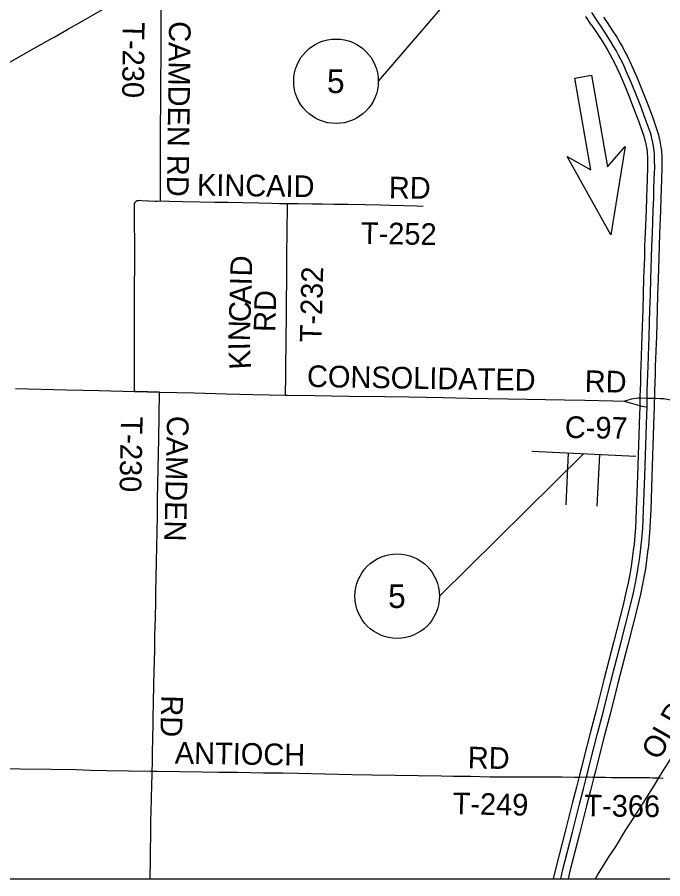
# Model space of a CAD drawing. Extents: x 1341221 to 1914484, y 79347 to 658398.
# Drawn here: x 1374791 to 1392220, y 580425 to 603681 of the extents above; entities that cross this region are included whole.
import ezdxf

# ---------------------------------------------------------------- set-up
doc = ezdxf.new("R2010")
doc.units = 0
for name, color, linetype in [('GM_X_County', 7, 'Continuous'), ('GM_X_County_Road_Text', 7, 'Continuous'), ('GM_X_Major_Lake_Text', 7, 'Continuous'), ('GM_X_Major_River_Text', 7, 'Continuous'), ('GM_X_Minor_Lake_Text', 7, 'Continuous'), ('GM_X_Minor_River', 7, 'Continuous'), ('GM_X_State_Location', 7, 'Continuous'), ('GM_X_Township_Road_Text', 7, 'Continuous'), ('GM_X_Township_Text', 7, 'Continuous'), ('GM_X_Unincorporated', 7, 'Continuous'), ('GM_X_US_Shield', 7, 'Continuous')]:
    doc.layers.add(name, color=color, linetype=linetype)

msp = doc.modelspace()

# ---------------------------------------------------------------- linework, layer by layer
at = {"layer": 'GM_X_County'}
msp.add_line((1390297, 603467), (1390145, 603700), dxfattribs=at)
for points in [[(1390624, 603681), (1390719, 603535), (1390865, 603315), (1390977, 603139), (1391072, 602981), (1391131, 602878), (1391200, 602751), (1391256, 602643), (1391333, 602483), (1391414, 602304), (1391526, 602042), (1391672, 601684), (1391796, 601366), (1391930, 601018), (1392037, 600724), (1392072, 600613), (1392102, 600508), (1392127, 600409)], [(1390297, 603467), (1390394, 603320), (1390538, 603103), (1390645, 602934), (1390735, 602784), (1390790, 602687), (1390856, 602568), (1390906, 602470), (1390979, 602318), (1391057, 602147), (1391166, 601892), (1391310, 601539), (1391433, 601225), (1391565, 600881), (1391668, 600597), (1391699, 600501), (1391725, 600408), (1391748, 600315)], [(1391748, 600315), (1391750, 600309), (1391771, 600209), (1391786, 600117), (1391795, 600041), (1391801, 599975), (1391804, 599935)], [(1392127, 600409), (1392130, 600396), (1392154, 600282), (1392172, 600172), (1392183, 600082), (1392190, 600008), (1392193, 599967)], [(1391804, 599948), (1391806, 599823), (1391807, 599638), (1391797, 599308), (1391788, 599065), (1391780, 598815), (1391768, 598471)], [(1392194, 599954), (1392196, 599828), (1392197, 599634), (1392186, 599294), (1392178, 599051), (1392170, 598802), (1392158, 598457)], [(1391768, 598471), (1391744, 597858), (1391731, 597511), (1391724, 597191), (1391704, 596636), (1391691, 596194), (1391679, 595798), (1391657, 595083), (1391629, 594272), (1391622, 594055), (1391615, 593838), (1391606, 593593), (1391605, 593476)], [(1392157, 598456), (1392134, 597843), (1392121, 597499), (1392113, 597180), (1392094, 596623), (1392081, 596183), (1392069, 595786), (1392047, 595070), (1392019, 594259), (1392012, 594042), (1392005, 593825), (1391996, 593583), (1391994, 593470)], [(1391605, 593476), (1391603, 593403), (1391601, 593328)], [(1391601, 593325), (1391600, 593168), (1391593, 592965)], [(1391991, 593321), (1391990, 593160), (1391983, 592952)], [(1391994, 593470), (1391993, 593395), (1391991, 593318)], [(1391593, 592965), (1391537, 591298), (1391506, 590391), (1391495, 590118), (1391483, 589911), (1391466, 589686), (1391444, 589453), (1391425, 589285), (1391398, 589073), (1391366, 588856), (1391329, 588640), (1391284, 588412), (1391236, 588191), (1391147, 587820), (1390897, 586838), (1390628, 585799), (1390418, 584965), (1390271, 584396), (1390102, 583725), (1390026, 583428), (1389974, 583226)], [(1391983, 592952), (1391927, 591285), (1391896, 590376), (1391884, 590099), (1391872, 589885), (1391855, 589652), (1391832, 589413), (1391812, 589239), (1391785, 589020), (1391751, 588794), (1391712, 588569), (1391666, 588333), (1391616, 588104), (1391526, 587727), (1391275, 586741), (1391006, 585703), (1390796, 584869), (1390649, 584299), (1390480, 583629), (1390404, 583331), (1390352, 583129)], [(1389974, 583226), (1389890, 582902), (1389785, 582490), (1389594, 581735), (1389336, 580725), (1389264, 580425)], [(1390352, 583128), (1390268, 582805), (1390163, 582393), (1389972, 581639), (1389715, 580631), (1389665, 580425)]]:
    msp.add_lwpolyline(points, dxfattribs=at)
for centre in [(1383398, 601952), (1385049, 588054)]:
    msp.add_circle(centre, 1141, dxfattribs=at)
at = {"layer": 'GM_X_County_Road_Text'}
for p, q in [((1387422, 605318), (1384539, 601952)), ((1386190, 588054), (1390089, 591901))]:
    msp.add_line(p, q, dxfattribs=at)
at = {"layer": 'GM_X_Minor_Lake_Text'}
msp.add_lwpolyline([(1435650, 641695), (1348099, 641695), (1348099, 580425), (1435650, 580425)], close=True, dxfattribs=at)
at = {"layer": 'GM_X_Minor_River'}
for p, q in [((1388686, 591966), (1391491, 591836)), ((1389668, 591920), (1389603, 590518)), ((1390089, 591901), (1390089, 591901)), ((1390089, 591901), (1390089, 591901)), ((1390510, 591881), (1390444, 590479))]:
    msp.add_line(p, q, dxfattribs=at)
at = {"layer": 'GM_X_State_Location'}
msp.add_lwpolyline([(1369197, 599284), (1369239, 599316), (1369336, 599389), (1369617, 599601), (1369739, 599687), (1369792, 599722), (1369899, 599790), (1370152, 599941), (1371027, 600446), (1371722, 600842), (1372205, 601120), (1372852, 601483), (1373372, 601772), (1375078, 602744), (1375736, 603114), (1375804, 603153), (1376176, 603363), (1376498, 603548), (1376965, 603813), (1377238, 603969), (1378266, 604560), (1378605, 604754)], dxfattribs=at)
at = {"layer": 'GM_X_Township_Road_Text'}
for p, q in [((1389844, 602037), (1390294, 602115)), ((1390294, 602115), (1390726, 599643)), ((1390276, 599565), (1389844, 602037)), ((1390069, 602076), (1390069, 602076)), ((1390726, 599643), (1391203, 600190)), ((1391203, 600190), (1390815, 597806)), ((1390815, 597806), (1389642, 599917)), ((1389642, 599917), (1390276, 599565)), ((1390815, 597806), (1390815, 597806))]:
    msp.add_line(p, q, dxfattribs=at)
at = {"layer": 'GM_X_Township_Text'}
for points in [[(1378657, 598745), (1378656, 598778), (1378658, 599145), (1378659, 600047), (1378658, 600341), (1378663, 600917), (1378665, 601153), (1378667, 601518), (1378671, 601934), (1378671, 602151), (1378674, 602407), (1378673, 602605), (1378673, 602784), (1378674, 603085), (1378675, 603411), (1378677, 603782), (1378678, 603955)], [(1377956, 593575), (1377956, 593612), (1377958, 594006), (1377961, 594685), (1377960, 595018), (1377958, 595402), (1377958, 595600), (1377958, 595901), (1377959, 596144), (1377960, 596476), (1377964, 596918), (1377967, 597219), (1377965, 597564), (1377960, 598159), (1377956, 598614), (1377957, 598638), (1377960, 598650), (1377964, 598666), (1377969, 598678), (1377975, 598688), (1377982, 598698), (1377992, 598709), (1377999, 598715), (1378007, 598721), (1378016, 598725), (1378026, 598730), (1378033, 598731), (1378042, 598733), (1378058, 598736), (1378077, 598738), (1378117, 598739), (1378159, 598737), (1378519, 598718), (1378546, 598718), (1378569, 598719), (1378658, 598723), (1378657, 598745)], [(1378658, 598723), (1378902, 598715), (1379254, 598709), (1379721, 598699), (1380124, 598693), (1380482, 598685), (1380878, 598676), (1381326, 598667), (1381665, 598661), (1381876, 598657), (1382036, 598655), (1382090, 598654), (1382375, 598651), (1382765, 598644), (1383034, 598640), (1383341, 598638), (1383718, 598632), (1384172, 598624), (1384601, 598616), (1384869, 598611), (1385581, 598588), (1385748, 598584)], [(1382035, 593477), (1382036, 593566), (1382041, 593924), (1382047, 594391), (1382053, 594775), (1382056, 595164), (1382061, 595458), (1382062, 595867), (1382065, 596110), (1382068, 596500), (1382071, 596743), (1382071, 597236), (1382073, 597408), (1382078, 597766), (1382082, 598118), (1382084, 598336), (1382089, 598598), (1382090, 598654)], [(1378634, 593560), (1377985, 593574), (1377956, 593575)], [(1378378, 580425), (1378380, 580502), (1378382, 580585), (1378385, 580796), (1378389, 580962), (1378390, 581039), (1378393, 581275), (1378396, 581512), (1378398, 581722), (1378400, 581875), (1378402, 581983), (1378416, 582559), (1378425, 583007), (1378430, 583186), (1378434, 583333), (1378435, 583358), (1378440, 583518), (1378446, 583825), (1378459, 584611), (1378472, 585347), (1378475, 585500), (1378479, 585686), (1378502, 586612), (1378510, 586991), (1378523, 587468), (1378532, 587903), (1378537, 588152), (1378551, 588990), (1378565, 589783), (1378574, 590250), (1378582, 590660), (1378597, 591497), (1378612, 592297), (1378623, 592924), (1378634, 593538), (1378634, 593560)], [(1391179, 593319), (1391343, 593269), (1391588, 593197), (1391656, 593180), (1391712, 593172), (1391795, 593164)], [(1390400, 580425), (1390460, 580524), (1390780, 581041), (1390940, 581281), (1391227, 581742), (1391353, 581934), (1391548, 582239), (1391750, 582563), (1391996, 582952), (1392117, 583148), (1392216, 583316), (1392373, 583564), (1392682, 584057), (1392923, 584448), (1393198, 584911), (1393499, 585438), (1393767, 585919), (1393990, 586321), (1394248, 586787), (1394496, 587224), (1394866, 587888), (1395231, 588527), (1395270, 588607), (1395291, 588659)], [(1363822, 583611), (1364146, 583603), (1364677, 583592), (1365278, 583578), (1367657, 583528), (1369436, 583495), (1370389, 583483), (1370607, 583479), (1370751, 583483), (1371065, 583471), (1371565, 583460), (1372800, 583432), (1373171, 583426), (1373489, 583424), (1373823, 583414), (1374859, 583395), (1375709, 583387), (1376380, 583371), (1376765, 583357), (1377206, 583347), (1378378, 583333), (1378434, 583333)], [(1378434, 583333), (1378565, 583332), (1379773, 583314), (1380234, 583306), (1380733, 583300), (1381443, 583288), (1381961, 583284), (1382363, 583274), (1383825, 583240), (1384369, 583233), (1386242, 583206), (1386561, 583194), (1386895, 583198), (1387042, 583196), (1387284, 583186), (1387559, 583178), (1387783, 583175), (1387973, 583173), (1388167, 583178), (1388478, 583176), (1388672, 583177), (1389502, 583173), (1389834, 583171), (1389994, 583171), (1390163, 583177)], [(1390163, 583177), (1390208, 583174), (1390318, 583168), (1390676, 583166), (1390834, 583162), (1391124, 583159), (1391467, 583160), (1391863, 583157), (1391946, 583154), (1392117, 583148)], [(1392117, 583148), (1392233, 583143)]]:
    msp.add_lwpolyline(points, dxfattribs=at)
at = {"layer": 'GM_X_Unincorporated'}
msp.add_line((1390461, 603574), (1390308, 603807), dxfattribs=at)
for points in [[(1391937, 600362), (1391914, 600458), (1391886, 600557), (1391852, 600661), (1391747, 600949), (1391615, 601296), (1391491, 601611), (1391346, 601967), (1391235, 602226), (1391156, 602401), (1391081, 602557), (1391028, 602659), (1390961, 602783), (1390903, 602882), (1390811, 603036), (1390701, 603209), (1390557, 603427), (1390461, 603574)], [(1391999, 599951), (1391996, 599991), (1391989, 600062), (1391979, 600144), (1391962, 600246), (1391940, 600352), (1391937, 600362)], [(1391963, 598464), (1391975, 598809), (1391983, 599058), (1391992, 599301), (1392002, 599636), (1392001, 599826), (1391999, 599951)], [(1391800, 593473), (1391801, 593588), (1391810, 593831), (1391817, 594048), (1391824, 594266), (1391852, 595076), (1391874, 595792), (1391886, 596189), (1391899, 596630), (1391918, 597186), (1391926, 597505), (1391939, 597850), (1391963, 598464)], [(1391788, 592958), (1391795, 593164), (1391796, 593323)], [(1391796, 593323), (1391798, 593399), (1391800, 593473)], [(1390163, 583177), (1390215, 583380), (1390291, 583677), (1390460, 584347), (1390607, 584917), (1390817, 585751), (1391086, 586789), (1391337, 587774), (1391426, 588147), (1391475, 588372), (1391520, 588605), (1391558, 588825), (1391591, 589046), (1391619, 589262), (1391638, 589433), (1391660, 589669), (1391678, 589898), (1391690, 590109), (1391701, 590384), (1391732, 591291), (1391788, 592958)], [(1389464, 580425), (1389525, 580678), (1389783, 581687), (1389974, 582442), (1390079, 582853), (1390163, 583177)]]:
    msp.add_lwpolyline(points, dxfattribs=at)
at = {"layer": 'GM_X_US_Shield'}
for points in [[(1374742, 593659), (1376124, 593625), (1377006, 593603), (1377956, 593575)], [(1377956, 593575), (1377985, 593574), (1378634, 593560)], [(1378634, 593560), (1379564, 593540), (1380434, 593519), (1381156, 593499), (1382035, 593477), (1382084, 593476), (1382826, 593468), (1383273, 593459), (1383740, 593452), (1384706, 593440), (1385376, 593431), (1386291, 593414), (1386975, 593400), (1388037, 593380), (1389565, 593350), (1390115, 593340), (1390869, 593329), (1391179, 593319)], [(1391179, 593319), (1391262, 593345), (1391319, 593362), (1391372, 593376), (1391428, 593388), (1391503, 593399), (1391566, 593404), (1391629, 593404), (1391798, 593399)], [(1391798, 593399), (1392024, 593394), (1392151, 593389)], [(1392151, 593389), (1392247, 593386), (1392292, 593381), (1392336, 593375), (1392385, 593363), (1392518, 593326), (1392563, 593314)]]:
    msp.add_lwpolyline(points, dxfattribs=at)

# ---------------------------------------------------------------- texts
at = {"layer": 'GM_X_County'}
for p in [(1383154, 601633), (1384805, 587735)]:
    msp.add_text('5', height=639, dxfattribs=at).set_placement(p)
at = {"layer": 'GM_X_Major_Lake_Text'}
for s, rotation, p in [('CONSOLIDATED', 359.0198, (1382610, 593702)), ('RD', 359.0128, (1390109, 593565)), ('C-97', 358.9714, (1389572, 592327))]:
    msp.add_text(s, height=585, rotation=rotation, dxfattribs=at).set_placement(p)
at = {"layer": 'GM_X_Major_River_Text'}
for s, rotation, p in [('T-230', 269.4383, (1377644, 603546)), ('CAMDEN RD', 269.3098, (1378890, 603576)), ('KINCAID', 359.1861, (1379641, 598867)), ('RD', 359.5064, (1384822, 598790)), ('T-252', 359.1579, (1384067, 597562)), ('D', 88.3277, (1381125, 596678)), ('T-232', 88.5977, (1383004, 594899)), ('I', 88.3274, (1381118, 596438)), ('A', 88.3277, (1381103, 595923)), ('RD', 88.5189, (1381759, 595178)), ('C', 88.3283, (1381089, 595443)), ('N', 88.3769, (1381075, 594929)), ('I', 91.294, (1381080, 594696)), ('K', 92.9274, (1381106, 594187)), ('T-230', 268.8765, (1377593, 592908)), ('CAMDEN', 268.7304, (1378838, 592926)), ('OLD CAMDEN', 60.4221, (1392119, 583598)), ('RD', 268.5189, (1378684, 585384)), ('ANTIOCH', 359.0833, (1379041, 583535)), ('RD', 359.0109, (1386952, 583406)), ('T-249', 358.8762, (1386542, 582169)), ('T-366', 359.4159, (1390102, 582110))]:
    msp.add_text(s, height=585, rotation=rotation, dxfattribs=at).set_placement(p)

doc.saveas('drawing.dxf')
